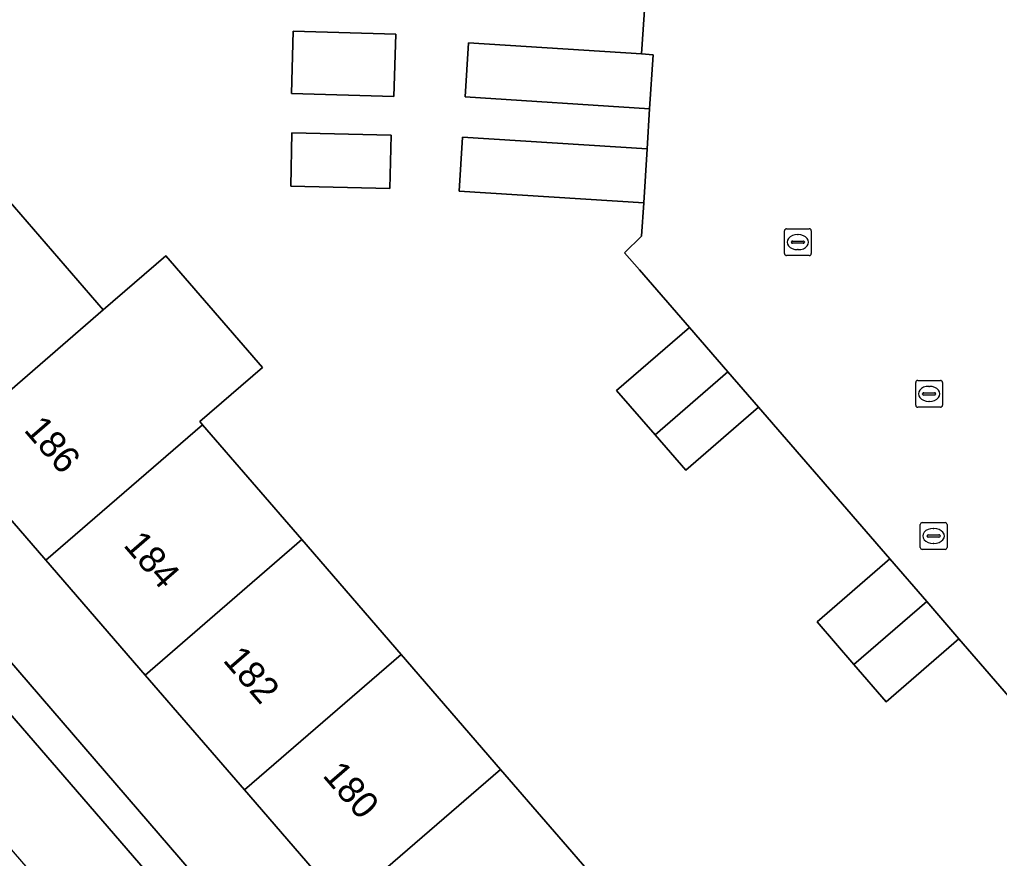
# Model space of a CAD drawing. Extents: x 160304 to 160955, y 383684 to 384161.
# Drawn here: x 160379.96 to 160416.53, y 384024.37 to 384055.67 of the extents above; entities that cross this region are included whole.
import ezdxf

# ---------------------------------------------------------------- set-up
doc = ezdxf.new("R2010")
doc.units = 0
for name, color, linetype in [('IMGEO_Erf', 7, 'Continuous'), ('IMGEO_Kolk', 7, 'Continuous'), ('IMGEO_Pand', 7, 'Continuous'), ('IMGEO_Pand_nummerreeks', 7, 'Continuous'), ('IMGEO_Rijbaan_lokaal_open', 7, 'Continuous'), ('IMGEO_Rioolput', 7, 'Continuous'), ('IMGEO_Voetpad_open', 7, 'Continuous')]:
    doc.layers.add(name, color=color, linetype=linetype)

msp = doc.modelspace()

# ---------------------------------------------------------------- linework, layer by layer
at = {"layer": 'IMGEO_Erf'}
for points in [[(160419.854, 384026.979), (160415.02, 384032.564), (160412.304, 384030.213), (160411.101, 384031.603), (160409.724, 384033.194), (160412.44, 384035.545), (160407.541, 384041.205), (160404.825, 384038.854), (160403.681, 384040.175), (160402.244, 384041.836), (160404.96, 384044.187), (160403.098, 384046.337), (160402.534, 384046.969), (160403.177, 384047.585), (160403.256, 384048.833), (160396.37, 384049.269), (160396.498, 384051.284), (160403.384, 384050.848), (160403.478, 384052.346), (160396.592, 384052.782), (160396.72, 384054.797), (160403.177, 384054.388), (160403.305, 384056.397)], [(160379.304, 384049.215), (160383.087, 384044.841), (160385.422, 384046.86), (160389.03, 384042.688), (160386.695, 384040.669), (160386.794, 384040.554), (160390.502, 384036.266), (160394.207, 384031.981), (160397.915, 384027.693), (160401.622, 384023.407), (160405.329, 384019.12), (160409.036, 384014.833), (160412.742, 384010.547), (160416.449, 384006.26), (160419.459, 384008.862)], [(160366.633, 384046.782), (160406.925, 384000), (160415.887, 383989.594), (160418.503, 383989.954)], [(160418.094, 383992.539), (160414.309, 383996.917), (160411.643, 384000), (160410.602, 384001.204), (160406.895, 384005.491), (160403.188, 384009.778), (160399.482, 384014.064), (160395.775, 384018.351), (160392.068, 384022.638), (160388.361, 384026.925), (160384.655, 384031.211), (160380.948, 384035.498), (160377.241, 384039.785)]]:
    msp.add_lwpolyline(points, dxfattribs=at)
for points in [[(160390.108, 384052.908), (160390.173, 384055.233), (160394, 384055.125), (160393.935, 384052.8)], [(160390.083, 384049.455), (160390.13, 384051.449), (160393.827, 384051.363), (160393.781, 384049.369)]]:
    msp.add_lwpolyline(points, close=True, dxfattribs=at)
at = {"layer": 'IMGEO_Kolk'}
for p, q in [((160408.508, 384046.94), (160408.508, 384047.792)), ((160408.583, 384047.866), (160409.435, 384047.866)), ((160408.996, 384047.646), (160409.021, 384047.646)), ((160409.509, 384047.792), (160409.509, 384046.94)), ((160408.767, 384047.36), (160408.767, 384047.372)), ((160409.205, 384047.323), (160408.807, 384047.323)), ((160408.81, 384047.409), (160409.208, 384047.409)), ((160409.251, 384047.372), (160409.251, 384047.36)), ((160409.019, 384047.086), (160408.994, 384047.086)), ((160409.435, 384046.866), (160408.583, 384046.866)), ((160413.482, 384042.206), (160414.334, 384042.206)), ((160413.407, 384041.28), (160413.407, 384042.132)), ((160413.895, 384041.986), (160413.92, 384041.986)), ((160414.408, 384042.132), (160414.408, 384041.28)), ((160413.666, 384041.7), (160413.666, 384041.712)), ((160414.104, 384041.663), (160413.706, 384041.663)), ((160413.709, 384041.749), (160414.107, 384041.749)), ((160413.918, 384041.426), (160413.893, 384041.426)), ((160414.15, 384041.712), (160414.15, 384041.7)), ((160414.334, 384041.206), (160413.482, 384041.206))]:
    msp.add_line(p, q, dxfattribs=at)
for points in [[(160408.508, 384046.94), (160408.508, 384047.792)], [(160408.583, 384047.866), (160409.435, 384047.866)], [(160409.509, 384047.792), (160409.509, 384046.94)], [(160409.435, 384046.866), (160408.583, 384046.866)], [(160413.482, 384042.206), (160414.334, 384042.206)], [(160413.407, 384041.28), (160413.407, 384042.132)], [(160414.408, 384042.132), (160414.408, 384041.28)], [(160414.334, 384041.206), (160413.482, 384041.206)]]:
    msp.add_lwpolyline(points, dxfattribs=at)
for centre, radius, start, end in [((160408.585, 384047.79), 0.0765, 91.552, 178.448), ((160408.585, 384047.79), 0.0765, 91.552, 178.448), ((160409.433, 384047.79), 0.0765, 1.552, 88.448), ((160409.433, 384047.79), 0.0765, 1.552, 88.448), ((160408.807, 384047.369), 0.0403, 85.8775, 175.7526), ((160408.804, 384047.359), 0.0366, 178.938, 274.7102), ((160409.208, 384047.366), 0.043, 264.8664, 352.4533), ((160409.212, 384047.371), 0.0386, 1.7309, 96.639), ((160408.585, 384046.942), 0.0765, 181.552, 268.448), ((160408.585, 384046.942), 0.0765, 181.552, 268.448), ((160409.433, 384046.942), 0.0765, 271.552, 358.448), ((160409.433, 384046.942), 0.0765, 271.552, 358.448), ((160413.484, 384042.13), 0.0765, 91.552, 178.448), ((160413.484, 384042.13), 0.0765, 91.552, 178.448), ((160414.332, 384042.13), 0.0765, 1.552, 88.448), ((160414.332, 384042.13), 0.0765, 1.552, 88.448), ((160413.706, 384041.709), 0.0403, 85.8775, 175.7526), ((160413.703, 384041.699), 0.0366, 178.938, 274.7102), ((160414.107, 384041.706), 0.043, 264.8664, 352.4533), ((160414.111, 384041.711), 0.0386, 1.7309, 96.639), ((160413.484, 384041.282), 0.0765, 181.552, 268.448), ((160413.484, 384041.282), 0.0765, 181.552, 268.448), ((160414.332, 384041.282), 0.0765, 271.552, 358.448), ((160414.332, 384041.282), 0.0765, 271.552, 358.448)]:
    msp.add_arc(centre, radius, start, end, dxfattribs=at)
for centre, major_axis, ratio, start_param, end_param in [((160408.995, 384047.366), (-0.387, 0.002), 0.722429, 4.712389, 7.853982), ((160409.02, 384047.366), (-0.39, 0.002), 0.717154, 1.570796, 4.712389), ((160413.894, 384041.706), (-0.387, 0.002), 0.722429, 4.712389, 7.853982), ((160413.919, 384041.706), (-0.39, 0.002), 0.717154, 1.570796, 4.712389)]:
    msp.add_ellipse(centre, major_axis=major_axis, ratio=ratio, start_param=start_param, end_param=end_param, dxfattribs=at)
at = {"layer": 'IMGEO_Pand'}
for points in [[(160394, 384055.125), (160390.173, 384055.233), (160390.108, 384052.908), (160393.935, 384052.8)], [(160403.606, 384054.361), (160403.177, 384054.388), (160396.72, 384054.797), (160396.592, 384052.782), (160403.478, 384052.346)], [(160393.827, 384051.363), (160390.13, 384051.449), (160390.083, 384049.455), (160393.781, 384049.369)], [(160403.256, 384048.833), (160403.384, 384050.848), (160396.498, 384051.284), (160396.37, 384049.269)], [(160383.087, 384044.841), (160379.304, 384049.215), (160373.455, 384044.164), (160377.241, 384039.785)], [(160386.794, 384040.554), (160386.695, 384040.669), (160389.03, 384042.688), (160385.422, 384046.86), (160383.087, 384044.841), (160377.241, 384039.785), (160380.948, 384035.498)], [(160406.399, 384042.525), (160404.96, 384044.187), (160402.244, 384041.836), (160403.681, 384040.175)], [(160406.399, 384042.525), (160403.681, 384040.175), (160404.825, 384038.854), (160407.541, 384041.205)], [(160386.794, 384040.554), (160380.948, 384035.498), (160384.655, 384031.211), (160390.502, 384036.266)], [(160388.361, 384026.925), (160394.207, 384031.981), (160390.502, 384036.266), (160384.655, 384031.211)], [(160413.818, 384033.953), (160412.44, 384035.545), (160409.724, 384033.194), (160411.101, 384031.603)], [(160413.818, 384033.953), (160411.101, 384031.603), (160412.304, 384030.213), (160415.02, 384032.564)], [(160388.361, 384026.925), (160392.068, 384022.638), (160397.915, 384027.693), (160394.207, 384031.981)], [(160397.915, 384027.693), (160392.068, 384022.638), (160395.775, 384018.351), (160401.622, 384023.407)]]:
    msp.add_lwpolyline(points, close=True, dxfattribs=at)
at = {"layer": 'IMGEO_Rijbaan_lokaal_open'}
msp.add_lwpolyline([(160403.305, 384056.397), (160403.177, 384054.388), (160403.606, 384054.361), (160403.478, 384052.346), (160403.384, 384050.848), (160403.256, 384048.833), (160403.177, 384047.585), (160402.534, 384046.969), (160403.098, 384046.337), (160404.96, 384044.187), (160406.399, 384042.525), (160407.541, 384041.205), (160412.44, 384035.545), (160413.818, 384033.953), (160415.02, 384032.564), (160419.854, 384026.979)], dxfattribs=at)
msp.add_lwpolyline([(160364.754, 384046.943), (160362.283, 384044.777), (160370.313, 384035.491), (160370.932, 384034.776), (160391.267, 384011.265), (160391.959, 384010.465), (160395.114, 384006.817), (160397.588, 384008.955)], close=True, dxfattribs=at)
at = {"layer": 'IMGEO_Rioolput'}
for p, q in [((160413.575, 384035.977), (160413.575, 384036.829)), ((160413.65, 384036.903), (160414.502, 384036.903)), ((160414.063, 384036.683), (160414.088, 384036.683)), ((160414.576, 384036.829), (160414.576, 384035.977)), ((160413.834, 384036.397), (160413.834, 384036.409)), ((160414.272, 384036.36), (160413.874, 384036.36)), ((160413.877, 384036.446), (160414.275, 384036.446)), ((160414.318, 384036.409), (160414.318, 384036.397)), ((160414.086, 384036.123), (160414.061, 384036.123)), ((160414.502, 384035.903), (160413.65, 384035.903))]:
    msp.add_line(p, q, dxfattribs=at)
for points in [[(160413.575, 384035.977), (160413.575, 384036.829)], [(160413.65, 384036.903), (160414.502, 384036.903)], [(160414.576, 384036.829), (160414.576, 384035.977)], [(160414.502, 384035.903), (160413.65, 384035.903)]]:
    msp.add_lwpolyline(points, dxfattribs=at)
for centre, radius, start, end in [((160413.652, 384036.827), 0.0765, 91.552, 178.448), ((160413.652, 384036.827), 0.0765, 91.552, 178.448), ((160414.5, 384036.827), 0.0765, 1.552, 88.448), ((160414.5, 384036.827), 0.0765, 1.552, 88.448), ((160413.874, 384036.406), 0.0403, 85.8775, 175.7526), ((160413.871, 384036.396), 0.0366, 178.938, 274.7102), ((160414.275, 384036.403), 0.043, 264.8664, 352.4533), ((160414.279, 384036.408), 0.0386, 1.7309, 96.639), ((160413.652, 384035.979), 0.0765, 181.552, 268.448), ((160413.652, 384035.979), 0.0765, 181.552, 268.448), ((160414.5, 384035.979), 0.0765, 271.552, 358.448), ((160414.5, 384035.979), 0.0765, 271.552, 358.448)]:
    msp.add_arc(centre, radius, start, end, dxfattribs=at)
for centre, major_axis, ratio, start_param, end_param in [((160414.062, 384036.403), (-0.387, 0.002), 0.722429, 4.712389, 7.853982), ((160414.087, 384036.403), (-0.39, 0.002), 0.717154, 1.570796, 4.712389)]:
    msp.add_ellipse(centre, major_axis=major_axis, ratio=ratio, start_param=start_param, end_param=end_param, dxfattribs=at)
at = {"layer": 'IMGEO_Voetpad_open'}
msp.add_lwpolyline([(160364.754, 384046.943), (160397.588, 384008.955), (160399.379, 384006.883), (160405.328, 384000), (160419.771, 383983.265), (160422.038, 383985.305), (160420.449, 383987.142), (160418.503, 383989.954), (160415.887, 383989.594), (160406.925, 384000), (160366.633, 384046.782)], dxfattribs=at)

# ---------------------------------------------------------------- texts
at = {"layer": 'IMGEO_Pand_nummerreeks'}
for s, p in [('186', (160380.093, 384040.343)), ('184', (160383.807, 384036.047)), ('182', (160387.521, 384031.752)), ('180', (160391.24, 384027.452))]:
    msp.add_text(s, height=1, rotation=310.8517, dxfattribs=at).set_placement(p)

doc.saveas('drawing.dxf')
